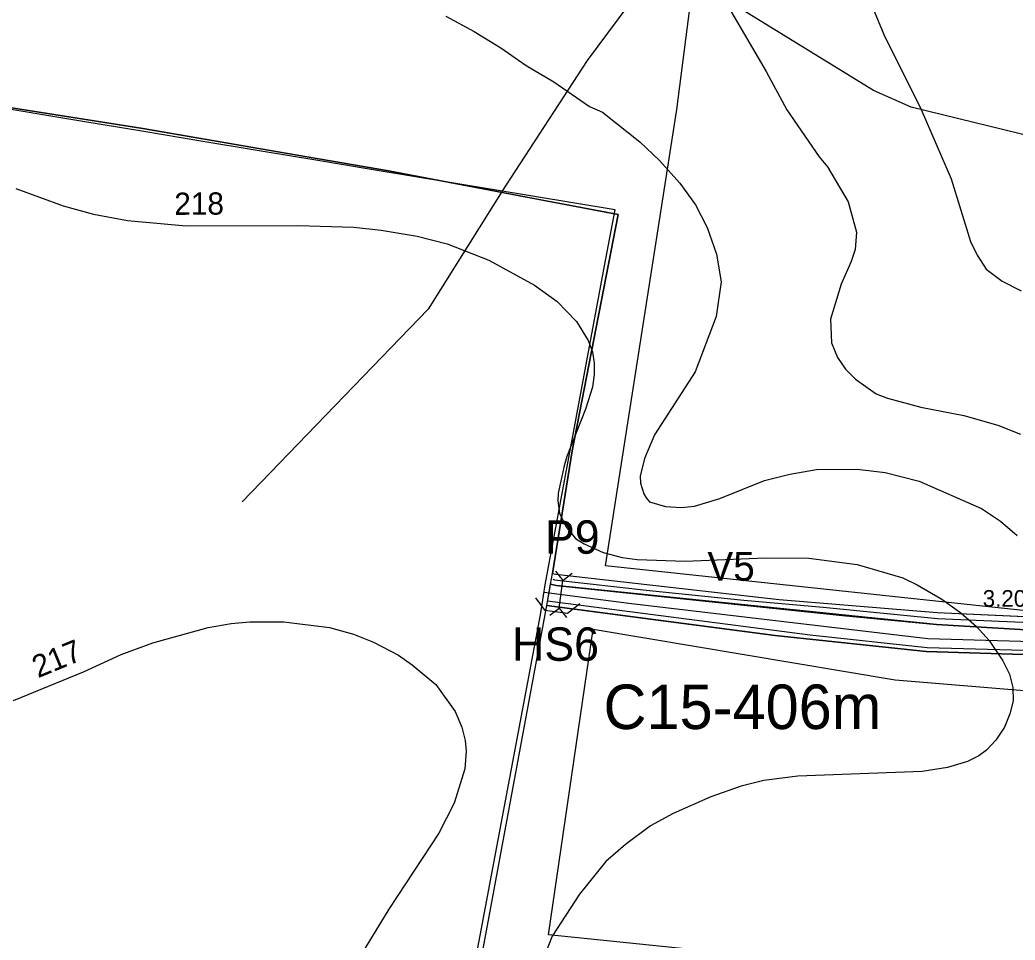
# Model space of a CAD drawing. Extents: x -662500 to -653478, y -1056827 to -1049993.
# Drawn here: x -660647.1 to -660199.8, y -1053979.7 to -1053566.3 of the extents above; entities that cross this region are included whole.
import ezdxf

# ---------------------------------------------------------------- set-up
doc = ezdxf.new("R2010")
doc.units = 0
for name, color, linetype in [('58', 7, 'Continuous'), ('Vrstva 1', 7, 'Continuous'), ('Vrstva 11', 7, 'Continuous'), ('Vrstva 17', 7, 'Continuous'), ('Vrstva 18', 7, 'Continuous'), ('Vrstva 24', 7, 'Continuous'), ('Vrstva 32', 7, 'Continuous'), ('Vrstva 37', 7, 'Continuous'), ('Vrstva 5', 7, 'Continuous'), ('Vrstva 57', 7, 'Continuous'), ('Vrstva 7', 7, 'Continuous')]:
    doc.layers.add(name, color=color, linetype=linetype)

# ---------------------------------------------------------------- blocks, each defined once
blk = doc.blocks.new('PSZ019')
at = {"layer": 'Vrstva 17'}
blk.add_lwpolyline([(-10, -5), (-5, 0), (5, 0), (10, -5)], dxfattribs=at)
blk = doc.blocks.new('PSZ017')
at = {"layer": 'Vrstva 17'}
for points in [[(-10, 3.75), (-6.25, 0), (-10, -3.75)], [(-6.25, 0), (6.25, 0)], [(10, 3.75), (6.25, 0), (10, -3.75)]]:
    blk.add_lwpolyline(points, dxfattribs=at)

msp = doc.modelspace()

# ---------------------------------------------------------------- linework, layer by layer
at = {"layer": '58'}
msp.add_lwpolyline([(-660445.86, -1054007.95), (-660413.19, -1053833.64), (-660411, -1053820.07), (-660384.31, -1053676.75), (-660379.64, -1053651.71), (-660490.15, -1053633.33), (-660513.22, -1053629.49), (-660539.56, -1053625.11), (-660565.82, -1053620.75), (-660592.33, -1053616.34), (-660618.84, -1053611.93), (-660635.87, -1053609.1), (-660659.17, -1053605.23)], dxfattribs=at)
at = {"layer": 'Vrstva 1'}
msp.add_lwpolyline([(-660438.94, -1053983.58), (-660410.34, -1053829.44), (-660408.79, -1053821.07), (-660408.56, -1053819.81), (-660407.77, -1053814.99), (-660398.86, -1053759.98), (-660378.28, -1053653.76), (-660412.36, -1053647.26), (-660481.41, -1053634.1), (-660522.43, -1053627.05), (-660591.82, -1053615.12), (-660653.75, -1053605.31), (-660728.84, -1053594.86), (-660735.74, -1053593.9), (-660749.01, -1053592.05)], dxfattribs=at)
at = {"layer": 'Vrstva 11'}
msp.add_lwpolyline([(-660411.52, -1053823.45), (-660373.44, -1053828.35), (-660238.99, -1053844.22), (-660171.25, -1053846.11), (-660139.82, -1053846.95), (-660035.43, -1053845.88), (-660005.55, -1053852.66)], dxfattribs=at)
at = {"layer": 'Vrstva 17'}
msp.add_lwpolyline([(-660409.95, -1053827.36), (-660292, -1053842.62), (-660239.28, -1053848.23), (-660146.85, -1053850.88), (-660072.84, -1053851.25)], dxfattribs=at)
at = {"layer": 'Vrstva 24'}
msp.add_lwpolyline([(-659687, -1053701.5), (-659711, -1053686.5), (-659734.5, -1053680.5), (-659814, -1053669.5), (-659908, -1053649.5), (-659980.14, -1053645.8), (-660000, -1053644.78), (-660005.5, -1053644.5), (-660060, -1053634), (-660183.5, -1053621), (-660246.5, -1053605.5), (-660263.5, -1053598), (-660330, -1053557), (-660364, -1053532.5), (-660389, -1053520), (-660401.5, -1053515), (-660430, -1053509.5)], dxfattribs=at)
at = {"layer": 'Vrstva 32'}
msp.add_lwpolyline([(-660407.56, -1053817.63), (-660406.83, -1053817.81), (-660364.13, -1053822.72), (-660321.75, -1053826.98), (-660286.16, -1053830.17), (-660234.71, -1053835.24), (-660175.64, -1053837.86), (-660158.79, -1053838.51), (-660151.75, -1053838.35), (-660149.96, -1053811.19), (-660141.45, -1053809.55), (-660090.4, -1053795.64), (-660046.88, -1053784.52)], dxfattribs=at)
at = {"layer": 'Vrstva 37'}
for points in [[(-660303.5, -1053230.44), (-660268.36, -1053230.44), (-660272.06, -1053456.27), (-660238.23, -1053464.08), (-660230.1, -1053441.95), (-660156.9, -1053423.64), (-660133.56, -1053315.41), (-660112.26, -1053315.31), (-660122.32, -1053372.39), (-660125.43, -1053404.18), (-660127.57, -1053442.13), (-660131.64, -1053497.5), (-660136.95, -1053566.03), (-660150.34, -1053712.33), (-660162.69, -1053835.19), (-660383.93, -1053811.56), (-660351.89, -1053606.5)], [(-660389.4, -1053839.98), (-660253.75, -1053862.77), (-660128.74, -1053873.18), (-660122.24, -1053853.65), (-660047.41, -1053856.91), (-660034.08, -1053884.58), (-659995.36, -1053877.42), (-659962.61, -1054026.33), (-660034.34, -1054033.17), (-660165.85, -1054002.41), (-660409.51, -1053977.34)]]:
    msp.add_lwpolyline(points, close=True, dxfattribs=at)
at = {"layer": 'Vrstva 5'}
for points in [[(-660659.38, -1053604.53), (-660591.82, -1053615.12), (-660481.41, -1053634.1), (-660378.28, -1053653.76), (-660398.86, -1053759.98), (-660407.77, -1053814.99), (-660406.28, -1053815.33), (-660305.92, -1053826.68), (-660234.87, -1053832.54), (-660162.97, -1053835.81), (-660159.44, -1053804.48), (-660157.5, -1053793.95), (-660158.49, -1053793), (-660150.34, -1053712.33), (-660136.95, -1053566.03)], [(-660157.09, -1053852.56), (-660239.81, -1053850.04), (-660307.68, -1053842.9), (-660410.34, -1053829.44), (-660408.56, -1053819.81), (-660406.12, -1053820.42), (-660337.51, -1053827.66), (-660277.44, -1053833.82), (-660235.12, -1053837.99), (-660159.73, -1053842.4)]]:
    msp.add_lwpolyline(points, dxfattribs=at)
for points in [[(-660407.77, -1053814.99), (-660406.28, -1053815.33), (-660305.92, -1053826.68), (-660234.87, -1053832.54), (-660159.25, -1053835.99), (-660159.73, -1053842.4), (-660235.12, -1053837.99), (-660406.12, -1053820.42), (-660408.56, -1053819.81)], [(-660410.34, -1053829.44), (-660358.01, -1053836.31), (-660307.68, -1053842.9), (-660239.81, -1053850.04), (-660157.09, -1053852.56), (-660122.2, -1053852.55), (-660088.98, -1053852.83), (-660073.51, -1053852.41), (-660070.7, -1053876.72), (-660055.8, -1053876.8), (-660042.1, -1053979.18), (-660077.54, -1053979.35), (-660076.72, -1054000.14), (-660201.14, -1054026.33), (-660241.12, -1054042.52), (-660324.21, -1054084.16), (-660365.41, -1054097.44), (-660421.6, -1054104.02), (-660440.68, -1054035.17), (-660444.92, -1054007.24), (-660438.94, -1053983.58)]]:
    msp.add_lwpolyline(points, close=True, dxfattribs=at)
at = {"layer": 'Vrstva 57'}
msp.add_lwpolyline([(-660161.77, -1053238.23), (-660180.21, -1053289.29), (-660196.67, -1053318.48), (-660229.8, -1053370.88), (-660276.09, -1053424.22), (-660304.29, -1053466.28), (-660392.17, -1053584.48), (-660428.83, -1053640.88), (-660463.61, -1053696.33), (-660547.26, -1053782.81)], dxfattribs=at)
at = {"layer": 'Vrstva 7'}
for p, q in [((-660337.8, -1053544.8), (-660311.72, -1053589.45)), ((-660265.8, -1053555.86), (-660258.86, -1053572.86)), ((-660455.65, -1053564.64), (-660442.95, -1053571.45)), ((-660442.95, -1053571.45), (-660430.9, -1053578.82)), ((-660258.86, -1053572.86), (-660242, -1053606.59)), ((-660430.9, -1053578.82), (-660419.57, -1053586.75)), ((-660419.57, -1053586.75), (-660407.1, -1053594.12)), ((-660311.72, -1053589.45), (-660302.37, -1053606.73)), ((-660407.1, -1053594.12), (-660391.08, -1053605.18)), ((-660391.08, -1053605.18), (-660385.27, -1053607.73)), ((-660385.27, -1053607.73), (-660368.41, -1053621.05)), ((-660302.37, -1053606.73), (-660287.91, -1053627.85)), ((-660242, -1053606.59), (-660228.53, -1053637.77)), ((-660368.41, -1053621.05), (-660359.62, -1053629.41)), ((-660359.62, -1053629.41), (-660350.55, -1053639.61)), ((-660287.91, -1053627.85), (-660284.09, -1053632.39)), ((-660284.09, -1053632.39), (-660274.87, -1053647.97)), ((-660350.55, -1053639.61), (-660343.46, -1053649.39)), ((-660228.53, -1053637.77), (-660219.89, -1053665.83)), ((-660648.86, -1053642.02), (-660627.61, -1053649.82)), ((-660627.61, -1053649.82), (-660614, -1053653.64)), ((-660343.46, -1053649.39), (-660338.22, -1053659.59)), ((-660274.87, -1053647.97), (-660271.05, -1053661.72)), ((-660614, -1053653.64), (-660598.7, -1053656.48)), ((-660598.7, -1053656.48), (-660572.34, -1053658.89)), ((-660572.34, -1053658.89), (-660522.17, -1053658.6)), ((-660522.17, -1053658.6), (-660496.94, -1053659.45)), ((-660496.94, -1053659.45), (-660484.76, -1053660.73)), ((-660484.76, -1053660.73), (-660468.6, -1053663.42)), ((-660468.6, -1053663.42), (-660455, -1053666.96)), ((-660338.22, -1053659.59), (-660333.97, -1053671.5)), ((-660271.05, -1053661.72), (-660271.76, -1053669.52)), ((-660455, -1053666.96), (-660436.29, -1053674.19)), ((-660219.89, -1053665.83), (-660216.91, -1053672.07)), ((-660333.97, -1053671.5), (-660331.99, -1053683.97)), ((-660271.76, -1053669.52), (-660273.46, -1053674.9)), ((-660216.91, -1053672.07), (-660212.8, -1053678.3)), ((-660436.29, -1053674.19), (-660415.88, -1053685.53)), ((-660273.46, -1053674.9), (-660277.99, -1053685.1)), ((-660212.8, -1053678.3), (-660205.58, -1053683.69)), ((-660415.88, -1053685.53), (-660405.68, -1053692.76)), ((-660331.99, -1053683.97), (-660334.11, -1053699.56)), ((-660277.99, -1053685.1), (-660282.81, -1053700.69)), ((-660205.58, -1053683.69), (-660197.07, -1053688.08)), ((-660405.68, -1053692.76), (-660396.89, -1053701.83)), ((-660396.89, -1053701.83), (-660391.65, -1053710.33)), ((-660334.11, -1053699.56), (-660343.61, -1053724.36)), ((-660282.81, -1053700.69), (-660282.39, -1053711.46)), ((-660391.65, -1053710.33), (-660389.81, -1053715.43)), ((-660282.39, -1053711.46), (-660279.69, -1053717.98)), ((-660389.81, -1053715.43), (-660388.96, -1053720.53)), ((-660388.96, -1053720.53), (-660388.96, -1053725.64)), ((-660279.69, -1053717.98), (-660276.01, -1053723.23)), ((-660388.96, -1053725.64), (-660389.81, -1053731.3)), ((-660343.61, -1053724.36), (-660361.89, -1053752.7)), ((-660276.01, -1053723.23), (-660271.61, -1053727.76)), ((-660271.61, -1053727.76), (-660262.26, -1053734.28)), ((-660389.81, -1053731.3), (-660392.92, -1053741.22)), ((-660262.26, -1053734.28), (-660257.16, -1053736.26)), ((-660257.16, -1053736.26), (-660242.14, -1053740.23)), ((-660392.92, -1053741.22), (-660401.29, -1053762.48)), ((-660242.14, -1053740.23), (-660222.86, -1053744.06)), ((-660222.86, -1053744.06), (-660207.56, -1053748.31)), ((-660207.56, -1053748.31), (-660197.35, -1053752.42)), ((-660361.89, -1053752.7), (-660366.42, -1053763.33)), ((-660401.29, -1053762.48), (-660402.56, -1053766.59)), ((-660366.42, -1053763.33), (-660368.27, -1053771.27)), ((-660402.56, -1053766.59), (-660405.25, -1053778.92)), ((-660312.43, -1053773.25), (-660301.09, -1053770.42)), ((-660301.09, -1053770.42), (-660289.05, -1053768.29)), ((-660289.05, -1053768.29), (-660270.77, -1053768.15)), ((-660270.77, -1053768.15), (-660258.29, -1053769.71)), ((-660258.29, -1053769.71), (-660242.99, -1053773.53)), ((-660368.27, -1053771.27), (-660368.12, -1053774.39)), ((-660368.12, -1053774.39), (-660366.71, -1053779.2)), ((-660332.55, -1053781.33), (-660312.43, -1053773.25)), ((-660242.99, -1053773.53), (-660214.93, -1053785.86)), ((-660405.25, -1053778.92), (-660405.4, -1053782.32)), ((-660366.71, -1053779.2), (-660365.64, -1053781.01)), ((-660405.4, -1053782.32), (-660404.55, -1053787.99)), ((-660365.64, -1053781.01), (-660364.16, -1053782.89)), ((-660364.16, -1053782.89), (-660356.93, -1053784.87)), ((-660343.89, -1053784.73), (-660332.55, -1053781.33)), ((-660404.55, -1053787.99), (-660401.71, -1053793.94)), ((-660356.93, -1053784.87), (-660349.79, -1053785.33)), ((-660349.79, -1053785.33), (-660343.89, -1053784.73)), ((-660214.93, -1053785.86), (-660206.43, -1053791.53)), ((-660206.43, -1053791.53), (-660198.91, -1053797.91)), ((-660401.71, -1053793.94), (-660397.32, -1053799.33)), ((-660397.32, -1053799.33), (-660393.49, -1053801.74)), ((-660393.49, -1053801.74), (-660384.99, -1053805.56)), ((-660384.99, -1053805.56), (-660376.48, -1053807.83)), ((-660376.48, -1053807.83), (-660369.68, -1053808.68)), ((-660369.68, -1053808.68), (-660348.14, -1053809.53)), ((-660348.14, -1053809.53), (-660312.15, -1053807.97)), ((-660312.15, -1053807.97), (-660292.59, -1053808.11)), ((-660292.59, -1053808.11), (-660270.77, -1053810.95)), ((-660270.77, -1053810.95), (-660250.36, -1053816.9)), ((-660250.36, -1053816.9), (-660243.92, -1053820.12)), ((-660243.92, -1053820.12), (-660232.79, -1053826.54)), ((-660232.79, -1053826.54), (-660224.28, -1053832.63)), ((-660224.28, -1053832.63), (-660217.2, -1053838.87)), ((-660562.42, -1053839.29), (-660552.21, -1053837.45)), ((-660552.21, -1053837.45), (-660543.71, -1053836.74)), ((-660543.71, -1053836.74), (-660528.41, -1053836.74)), ((-660528.41, -1053836.74), (-660508, -1053839.29)), ((-660587.36, -1053846.24), (-660562.42, -1053839.29)), ((-660508, -1053839.29), (-660497.09, -1053842.27)), ((-660497.09, -1053842.27), (-660488.16, -1053845.81)), ((-660217.2, -1053838.87), (-660211.53, -1053845.1)), ((-660601.53, -1053851.48), (-660587.36, -1053846.24)), ((-660488.16, -1053845.81), (-660476.96, -1053851.76)), ((-660211.53, -1053845.1), (-660205.29, -1053854.31)), ((-660618.54, -1053859.13), (-660601.53, -1053851.48)), ((-660476.96, -1053851.76), (-660470.87, -1053856.01)), ((-660205.29, -1053854.31), (-660202.32, -1053860.27)), ((-660650, -1053872.03), (-660618.54, -1053859.13)), ((-660470.87, -1053856.01), (-660460.1, -1053864.94)), ((-660202.32, -1053860.27), (-660200.9, -1053866.22)), ((-660460.1, -1053864.94), (-660451.45, -1053876.99)), ((-660200.9, -1053866.22), (-660200.76, -1053872.17)), ((-660200.76, -1053872.17), (-660202.17, -1053878.12)), ((-660451.45, -1053876.99), (-660448.48, -1053884.07)), ((-660202.17, -1053878.12), (-660204.58, -1053884.07)), ((-660448.48, -1053884.07), (-660446.92, -1053890.03)), ((-660204.58, -1053884.07), (-660208.55, -1053889.88)), ((-660446.92, -1053890.03), (-660446.49, -1053894.84)), ((-660208.55, -1053889.88), (-660212.66, -1053894.42)), ((-660446.49, -1053894.84), (-660447.06, -1053902.78)), ((-660212.66, -1053894.42), (-660216.06, -1053896.97)), ((-660221.16, -1053899.52), (-660230.23, -1053902.21)), ((-660216.06, -1053896.97), (-660221.16, -1053899.52)), ((-660447.06, -1053902.78), (-660451.88, -1053918.23)), ((-660241.57, -1053903.91), (-660297.41, -1053906.04)), ((-660230.23, -1053902.21), (-660241.57, -1053903.91)), ((-660312.71, -1053908.02), (-660322.92, -1053910.57)), ((-660297.41, -1053906.04), (-660312.71, -1053908.02)), ((-660322.92, -1053910.57), (-660336.52, -1053915.39)), ((-660451.88, -1053918.23), (-660458.82, -1053931.69)), ((-660336.52, -1053915.39), (-660353.53, -1053922.9)), ((-660353.53, -1053922.9), (-660363.73, -1053928.43)), ((-660458.82, -1053931.69), (-660481.35, -1053965.84)), ((-660363.73, -1053928.43), (-660374.93, -1053936.79)), ((-660374.93, -1053936.79), (-660383.71, -1053944.45)), ((-660383.71, -1053944.45), (-660395.62, -1053959.04)), ((-660395.62, -1053959.04), (-660407.95, -1053977.89)), ((-660481.35, -1053965.84), (-660492.12, -1053983.56)), ((-660407.95, -1053977.89), (-660411.2, -1053986.39))]:
    msp.add_line(p, q, dxfattribs=at)

# ---------------------------------------------------------------- block references
at = {"layer": 'Vrstva 17'}
for name, p, rotation in [('PSZ017', (-660403.91, -1053824.35), 82.54990316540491), ('PSZ019', (-660406, -1053832.26), 172.35543899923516)]:
    msp.add_blockref(name, p, dxfattribs=dict(at, rotation=rotation))

# ---------------------------------------------------------------- texts
for s, p in [('P9', (-660411.09, -1053806.14)), ('HS6', (-660425.86, -1053854.24))]:
    msp.add_text(s, height=15, rotation=360, dxfattribs=at).set_placement(p)
at = {"layer": 'Vrstva 18'}
msp.add_text('C15-406m', height=20, rotation=360, dxfattribs=at).set_placement((-660384.81, -1053884.91))
at = {"layer": 'Vrstva 24'}
msp.add_text('3.20.01', height=7.5, dxfattribs=at).set_placement((-660214.37, -1053829.97))
at = {"layer": 'Vrstva 32'}
msp.add_text('V5', height=13, rotation=360, dxfattribs=at).set_placement((-660338.11, -1053818.29))
at = {"layer": 'Vrstva 7'}
for s, rotation, p in [('218', 0.3232, (-660577.67, -1053653.91)), ('217', 22.2889, (-660638.97, -1053862.1))]:
    msp.add_text(s, height=10, rotation=rotation, dxfattribs=at).set_placement(p)

doc.saveas('drawing.dxf')
